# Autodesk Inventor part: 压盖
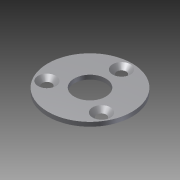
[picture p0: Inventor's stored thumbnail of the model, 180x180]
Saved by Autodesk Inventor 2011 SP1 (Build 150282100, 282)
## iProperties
Created: 2013-12
Part Number: 压盖
Document SubType Name: Modeling
Designer: Administrator
Density: 1 g/cm^3
Author: Administrator
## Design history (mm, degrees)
sketch "草图1"
  geometry: C1 r 7.5 at (0, 0); C2 r 20 at (0, 0); 1 further point
  constraints: 2 centre point, 2 coincident
  dimensions: "d0" = 15 diameter of C1; "d1" = 40 diameter of C2
extrude "拉伸1" new body sketch "草图1" distance "d2" = 2; taper "d3" = 0 deg
sketch "草图2"
  geometry: C1 r 7.5 at (0, 0) reference; 1 further point
  dimensions: "d4" = 15 distance of C1.centre point (0, 15)
hole "Hole1" sketch "草图2" at (0, 15) diameter "d5" = 4.5; stored, may be unused: countersink angle "d9" = 90 deg, drill point angle "d11" = 0 deg; dims "d6" = 6, "d7" = 8.5, "d8" = 2, "d10" = 8
pattern_circular "环形阵列1" dims angle "d13" = 360 deg
node "实体1"
node "工作轴1"
node "工作轴2"
